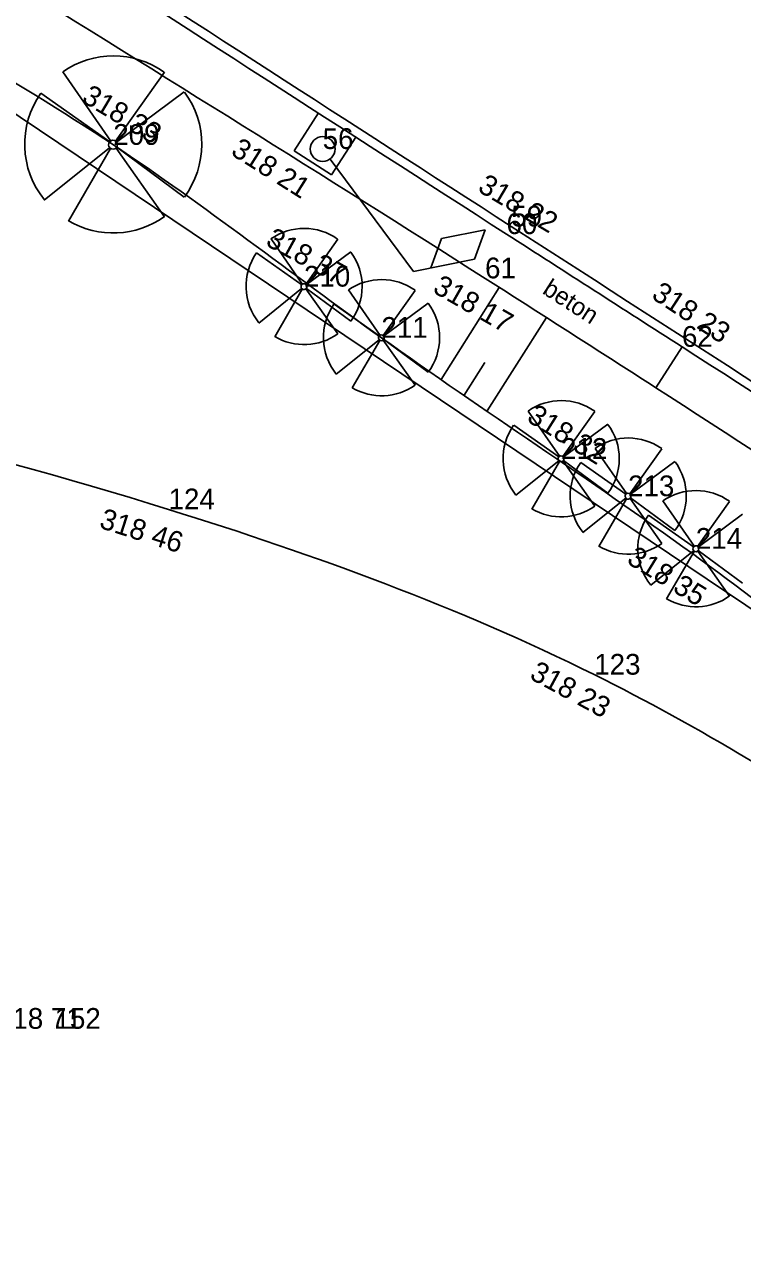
# Model space of a CAD drawing. Extents: x -742884 to -742543, y -1054677 to -1054433.
# Drawn here: x -742706.11 to -742695.71, y -1054513.42 to -1054495.74 of the extents above; entities that cross this region are included whole.
import ezdxf

# ---------------------------------------------------------------- set-up
doc = ezdxf.new("R2010")
doc.units = 0
for name, color, linetype in [('Vrstva 1', 7, 'Continuous'), ('Vrstva 10', 7, 'Continuous'), ('Vrstva 11', 7, 'Continuous'), ('Vrstva 12', 7, 'Continuous'), ('Vrstva 13', 7, 'Continuous'), ('Vrstva 15', 7, 'Continuous'), ('Vrstva 2', 7, 'Continuous'), ('Vrstva 3', 7, 'Continuous'), ('Vrstva 4', 7, 'Continuous'), ('Vrstva 50', 7, 'Continuous')]:
    doc.layers.add(name, color=color, linetype=linetype)

# ---------------------------------------------------------------- blocks, each defined once
blk = doc.blocks.new('Z15')
at = {"layer": 'Vrstva 2'}
for p, q in [((-10, 2), (-8, 6)), ((-10, -2), (-10, 2)), ((-8, 6), (-6, 8)), ((-6, 8), (-2, 10)), ((-2, 10), (2, 10)), ((2, 10), (6, 8)), ((6, 8), (8, 6)), ((8, 6), (10, 2)), ((10, 2), (10, -2)), ((-8, -6), (-10, -2)), ((-6, -8), (-8, -6)), ((-2, -10), (-6, -8)), ((2, -10), (-2, -10)), ((6, -8), (2, -10)), ((8, -6), (6, -8)), ((10, -2), (8, -6))]:
    blk.add_line(p, q, dxfattribs=at)

msp = doc.modelspace()

# ---------------------------------------------------------------- linework, layer by layer
at = {"layer": 'Vrstva 1'}
for p, q in [((-742704.82, -1054497.48), (-742704.82, -1054497.48)), ((-742701.79, -1054497.54), (-742701.79, -1054497.54)), ((-742699.06, -1054498.66), (-742699.06, -1054498.66)), ((-742699.13, -1054498.77), (-742699.13, -1054498.77)), ((-742699.44, -1054499.41), (-742699.44, -1054499.41)), ((-742702.06, -1054499.53), (-742702.06, -1054499.53)), ((-742700.94, -1054500.27), (-742700.94, -1054500.27)), ((-742696.59, -1054500.4), (-742696.59, -1054500.4)), ((-742698.34, -1054502.02), (-742698.34, -1054502.02)), ((-742697.37, -1054502.56), (-742697.37, -1054502.56)), ((-742704.02, -1054502.75), (-742704.02, -1054502.75)), ((-742696.39, -1054503.32), (-742696.39, -1054503.32)), ((-742697.86, -1054505.14), (-742697.86, -1054505.14)), ((-742705.67, -1054510.26), (-742705.67, -1054510.26))]:
    msp.add_line(p, q, dxfattribs=at)
at = {"layer": 'Vrstva 10'}
for p, q in [((-742704.853, -1054497.427), (-742705.55, -1054496.423)), ((-742704.786, -1054497.427), (-742704.08, -1054496.431)), ((-742704.872, -1054497.434), (-742705.867, -1054496.734)), ((-742704.775, -1054497.441), (-742703.792, -1054496.714)), ((-742704.874, -1054497.521), (-742705.818, -1054498.279)), ((-742704.862, -1054497.534), (-742705.467, -1054498.582)), ((-742704.78, -1054497.529), (-742704.078, -1054498.519)), ((-742704.769, -1054497.515), (-742703.792, -1054498.236)), ((-742702.08, -1054499.497), (-742702.537, -1054498.838)), ((-742702.035, -1054499.497), (-742701.572, -1054498.844)), ((-742702.093, -1054499.502), (-742702.745, -1054499.043)), ((-742702.028, -1054499.506), (-742701.384, -1054499.029)), ((-742702.094, -1054499.559), (-742702.713, -1054500.056)), ((-742702.085, -1054499.567), (-742702.482, -1054500.255)), ((-742702.032, -1054499.564), (-742701.571, -1054500.214)), ((-742702.024, -1054499.555), (-742701.384, -1054500.028)), ((-742700.96, -1054500.237), (-742701.417, -1054499.578)), ((-742700.915, -1054500.237), (-742700.452, -1054499.584)), ((-742700.973, -1054500.242), (-742701.625, -1054499.783)), ((-742700.908, -1054500.246), (-742700.264, -1054499.769)), ((-742700.974, -1054500.299), (-742701.593, -1054500.796)), ((-742700.965, -1054500.307), (-742701.362, -1054500.995)), ((-742700.912, -1054500.304), (-742700.451, -1054500.954)), ((-742700.904, -1054500.295), (-742700.264, -1054500.768)), ((-742698.36, -1054501.987), (-742698.817, -1054501.328)), ((-742698.315, -1054501.987), (-742697.852, -1054501.334)), ((-742698.373, -1054501.992), (-742699.025, -1054501.533)), ((-742698.308, -1054501.996), (-742697.664, -1054501.519)), ((-742697.39, -1054502.527), (-742697.847, -1054501.868)), ((-742697.345, -1054502.527), (-742696.882, -1054501.874)), ((-742698.374, -1054502.049), (-742698.993, -1054502.546)), ((-742698.365, -1054502.057), (-742698.762, -1054502.745)), ((-742698.312, -1054502.054), (-742697.851, -1054502.704)), ((-742698.304, -1054502.045), (-742697.664, -1054502.518)), ((-742697.403, -1054502.532), (-742698.055, -1054502.073)), ((-742697.338, -1054502.536), (-742696.694, -1054502.059)), ((-742697.404, -1054502.589), (-742698.023, -1054503.086)), ((-742697.395, -1054502.597), (-742697.792, -1054503.285)), ((-742697.342, -1054502.594), (-742696.881, -1054503.244)), ((-742697.334, -1054502.585), (-742696.694, -1054503.058)), ((-742696.41, -1054503.287), (-742696.867, -1054502.628)), ((-742696.365, -1054503.287), (-742695.902, -1054502.634)), ((-742696.423, -1054503.292), (-742697.075, -1054502.833)), ((-742696.358, -1054503.296), (-742695.714, -1054502.819)), ((-742696.424, -1054503.349), (-742697.043, -1054503.846)), ((-742696.415, -1054503.357), (-742696.812, -1054504.045)), ((-742696.362, -1054503.354), (-742695.901, -1054504.004)), ((-742696.354, -1054503.345), (-742695.714, -1054503.818))]:
    msp.add_line(p, q, dxfattribs=at)
for centre, radius, start, end in [((-742704.82, -1054497.474), 1.28, 54.7465, 124.8105), ((-742704.821, -1054497.471), 1.28, 144.8767, 218.9336), ((-742704.82, -1054497.474), 1.28, 323.4756, 36.2971), ((-742704.82, -1054497.474), 1.28, 239.6151, 305.4552), ((-742702.058, -1054499.528), 0.84, 54.7465, 124.8105), ((-742702.059, -1054499.526), 0.84, 144.8767, 218.9336), ((-742702.058, -1054499.528), 0.84, 323.4756, 36.2971), ((-742700.938, -1054500.268), 0.84, 54.7465, 124.8105), ((-742700.939, -1054500.266), 0.84, 144.8767, 218.9336), ((-742700.938, -1054500.268), 0.84, 323.4756, 36.2971), ((-742702.058, -1054499.528), 0.84, 239.6151, 305.4552), ((-742700.938, -1054500.268), 0.84, 239.6151, 305.4552), ((-742698.338, -1054502.018), 0.84, 54.7465, 124.8105), ((-742698.339, -1054502.016), 0.84, 144.8767, 218.9336), ((-742698.338, -1054502.018), 0.84, 323.4756, 36.2971), ((-742697.368, -1054502.558), 0.84, 54.7465, 124.8105), ((-742697.369, -1054502.556), 0.84, 144.8767, 218.9336), ((-742697.368, -1054502.558), 0.84, 323.4756, 36.2971), ((-742696.388, -1054503.318), 0.84, 54.7465, 124.8105), ((-742698.338, -1054502.018), 0.84, 239.6151, 305.4552), ((-742696.389, -1054503.316), 0.84, 144.8767, 218.9336), ((-742697.368, -1054502.558), 0.84, 239.6151, 305.4552), ((-742696.388, -1054503.318), 0.84, 239.6151, 305.4552)]:
    msp.add_arc(centre, radius, start, end, dxfattribs=at)
at = {"layer": 'Vrstva 11'}
for p, q in [((-742700.076, -1054500.871), (-742699.235, -1054499.541)), ((-742699.41, -1054501.327), (-742698.552, -1054499.978)), ((-742699.744, -1054501.099), (-742699.445, -1054500.629))]:
    msp.add_line(p, q, dxfattribs=at)
for points in [[(-742776.7, -1054542.68), (-742764.01, -1054527.79), (-742751.11, -1054512.75), (-742737.61, -1054496.47), (-742726.42, -1054483.98), (-742725.9, -1054484.03), (-742714, -1054491.86), (-742704.819, -1054497.481), (-742700.94, -1054500.269), (-742696.44, -1054503.39), (-742688.83, -1054509.5), (-742682.54, -1054514.17), (-742675.15, -1054519.77), (-742673.01, -1054522.11), (-742671.05, -1054524.7)], [(-742696.97, -1054500.991), (-742684.16, -1054509.32), (-742669.06, -1054519.4)], [(-742641.45, -1054542), (-742646.08, -1054542.32), (-742650.28, -1054545.1), (-742653.63, -1054549.14), (-742658.66, -1054557.13), (-742664.13, -1054565.84), (-742667.81, -1054569.62), (-742669.76, -1054570.07), (-742674.4, -1054567.88), (-742684.66, -1054562.03), (-742693.02, -1054556.88), (-742694.43, -1054554.37), (-742693.99, -1054552.67), (-742684.52, -1054539.64), (-742677.51, -1054529.95), (-742676.26, -1054526.54), (-742677.27, -1054522.39), (-742681.19, -1054517.29), (-742689.28, -1054510.73), (-742697.86, -1054505.14), (-742704.02, -1054502.75), (-742713.11, -1054501.07), (-742723.98, -1054503.51), (-742736.77, -1054510.1), (-742745.39, -1054515.75), (-742752.81, -1054521.82), (-742762.72, -1054531.38), (-742770.54, -1054539.36), (-742775.54, -1054544.64)]]:
    msp.add_spline(points, degree=3, dxfattribs=at)
at = {"layer": 'Vrstva 12'}
for p, q in [((-742702.201, -1054497.566), (-742701.849, -1054497.019)), ((-742701.66, -1054497.914), (-742701.308, -1054497.367)), ((-742702.201, -1054497.566), (-742701.66, -1054497.914))]:
    msp.add_line(p, q, dxfattribs=at)
for points in [[(-742701.682, -1054497.685), (-742700.475, -1054499.309)], [(-742700.072, -1054498.835), (-742699.437, -1054498.709)], [(-742699.591, -1054499.131), (-742699.437, -1054498.709)], [(-742700.226, -1054499.258), (-742700.072, -1054498.835)], [(-742700.475, -1054499.309), (-742699.591, -1054499.131)]]:
    msp.add_lwpolyline(points, dxfattribs=at)
msp.add_circle((-742701.79, -1054497.54), 0.18, dxfattribs=at)
at = {"layer": 'Vrstva 13'}
msp.add_line((-742696.97, -1054500.991), (-742696.59, -1054500.4), dxfattribs=at)
msp.add_spline([(-742725.15, -1054482.94), (-742713.48, -1054490.62), (-742699.44, -1054499.41), (-742696.97, -1054500.991)], degree=3, dxfattribs=at)
at = {"layer": 'Vrstva 4'}
for points in [[(-742718.8, -1054478.84), (-742709.4, -1054484.88), (-742695.99, -1054493.43), (-742680.4, -1054503.55), (-742661.01, -1054516), (-742635.78, -1054532.31)], [(-742668.427, -1054518.574), (-742683.74, -1054508.68), (-742696.59, -1054500.4), (-742699.13, -1054498.77), (-742713.15, -1054489.73), (-742724.623, -1054482.289)], [(-742668.31, -1054518.5), (-742683.67, -1054508.57), (-742699.06, -1054498.66), (-742713.08, -1054489.62), (-742724.57, -1054482.17)]]:
    msp.add_spline(points, degree=3, dxfattribs=at)
at = {"layer": 'Vrstva 50'}
msp.add_lwpolyline([(-742724.95, -1054484.46), (-742672.19, -1054519.91), (-742671.42, -1054521.73), (-742671.38, -1054524.18), (-742670.45, -1054526.06)], dxfattribs=at)

# ---------------------------------------------------------------- block references
at = {"layer": 'Vrstva 10'}
for p, xscale, yscale, rotation in [((-742704.823, -1054497.478), 0.006398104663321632, 0.006398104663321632, -30.671756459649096), ((-742702.06, -1054499.53), 0.004197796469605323, 0.004197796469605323, -30.671756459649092), ((-742700.94, -1054500.27), 0.004197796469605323, 0.004197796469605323, -30.671756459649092), ((-742698.34, -1054502.02), 0.004197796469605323, 0.004197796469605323, -30.671756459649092), ((-742697.37, -1054502.56), 0.004197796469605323, 0.004197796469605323, -30.671756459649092), ((-742696.39, -1054503.32), 0.004197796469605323, 0.004197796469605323, -30.671756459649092)]:
    msp.add_blockref('Z15', p, dxfattribs=dict(at, xscale=xscale, yscale=yscale, rotation=rotation))

# ---------------------------------------------------------------- texts
at = {"layer": 'Vrstva 15'}
msp.add_text('beton', height=0.256, rotation=327.2766, dxfattribs=at).set_placement((-742698.625, -1054499.62))
at = {"layer": 'Vrstva 2'}
for s, p in [('209', (-742704.82, -1054497.48)), ('56', (-742701.79, -1054497.54)), ('59', (-742699.06, -1054498.66)), ('60', (-742699.13, -1054498.77)), ('210', (-742702.06, -1054499.53)), ('61', (-742699.44, -1054499.41)), ('211', (-742700.94, -1054500.27)), ('62', (-742696.59, -1054500.4)), ('212', (-742698.34, -1054502.02)), ('213', (-742697.37, -1054502.56)), ('124', (-742704.02, -1054502.75)), ('214', (-742696.39, -1054503.32)), ('123', (-742697.86, -1054505.14)), ('152', (-742705.67, -1054510.26))]:
    msp.add_text(s, height=0.3, dxfattribs=at).set_placement(p)
at = {"layer": 'Vrstva 3'}
for s, rotation, p in [('318 33 ', 329.1305, (-742705.293, -1054496.851)), ('318 21 ', 327.7387, (-742703.134, -1054497.614)), ('318 22 ', 329.399, (-742699.562, -1054498.142)), ('318 37 ', 331.2349, (-742702.631, -1054498.925)), ('318 17 ', 330.2816, (-742700.213, -1054499.604)), ('318 23 ', 326.7576, (-742697.047, -1054499.69)), ('318 32 ', 327.875, (-742698.852, -1054501.465)), ('318 46 ', 342.3203, (-742705.037, -1054503.013)), ('318 35 ', 328.3925, (-742697.405, -1054503.519)), ('318 23 ', 331.5398, (-742698.811, -1054505.191))]:
    msp.add_text(s, height=0.3, rotation=rotation, dxfattribs=at).set_placement(p)
msp.add_text('318 71 ', height=0.3, dxfattribs=at).set_placement((-742706.503, -1054510.26))

doc.saveas('drawing.dxf')
